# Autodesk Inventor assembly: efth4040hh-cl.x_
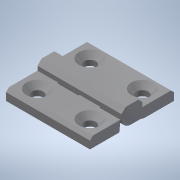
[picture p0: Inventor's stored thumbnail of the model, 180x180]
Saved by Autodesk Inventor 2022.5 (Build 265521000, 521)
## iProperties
Part Number: efth4040hh-cl.x_
Material: 一般
Document SubType Name: Assembly
Designer: ImaoCorp
Sending System: SOLIDWORKS 2017-2017317
MC: AMD64
MC_MODEL: Intel64 Family 6 Model 60 Stepping 3, GenuineIntel
OS: Windows_NT
FRU: Parasolid Version 29.0, build 201,  4-17-2017
FORMAT: text
GUISE: transmit
KEY: efth4040hh-cl
FILE: efth4040hh-cl.x_t
DATE: Mon May 13 14:22:21 2019
Author: ImaoCorp
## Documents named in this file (4)
- X:\14_SW2022-Inv2022\00_全2023-1023新製品(TCC)まで\e\efth4040hh-cl\EFTH4040HH-CL.iam
- X:\14_SW2022-Inv2022\00_全2023-1023新製品(TCC)まで\e\efth4040hh-cl\efth4040hh-cl_01.ipt
- X:\14_SW2022-Inv2022\00_全2023-1023新製品(TCC)まで\e\efth4040hh-cl\efth4040hh-cl_02.ipt
- X:\14_SW2022-Inv2022\00_全2023-1023新製品(TCC)まで\e\efth4040hh-cl\efth4040hh-cl_03.ipt
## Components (3 placed, 3 different names)
1. efth4040hh-cl_01
2. efth4040hh-cl_02
3. efth4040hh-cl_03
